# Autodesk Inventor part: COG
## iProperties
Created: 2010-11
Part Number: COG
Document SubType Name: Modeling
Designer: ROBERT
Density: 1 g/cm^3
Author: ROBERT
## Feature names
1. Extrusion1
2. Extrusion2
3. Circular Pattern1
4. Extrusion3
5. Circular Pattern2
6. Fillet1
